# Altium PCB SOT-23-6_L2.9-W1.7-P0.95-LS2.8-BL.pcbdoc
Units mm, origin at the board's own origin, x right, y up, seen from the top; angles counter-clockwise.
Board outline 15.98 x 15.98 mm, 2 copper layers (Top Layer, Bottom Layer), stack 0 mm thick; 1 components, 0 nets, 6 pads, 0 vias.
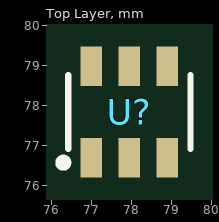
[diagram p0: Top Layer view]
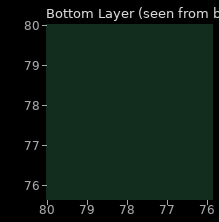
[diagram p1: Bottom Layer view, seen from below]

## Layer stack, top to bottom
Top Layer: signal copper (thickness not stored)
Bottom Layer: signal copper (thickness not stored)

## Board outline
85.827,69.85 69.85,69.85 69.85,85.83 85.827,85.83

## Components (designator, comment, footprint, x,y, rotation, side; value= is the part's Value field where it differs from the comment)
U? "" SOT-23-6_L2.9-W1.7-P0.95-LS2.8-BL 77.951,77.84 r0 top

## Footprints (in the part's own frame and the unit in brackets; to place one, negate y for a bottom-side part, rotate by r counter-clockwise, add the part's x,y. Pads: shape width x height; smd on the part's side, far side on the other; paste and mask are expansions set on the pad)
SOT-23-6_L2.9-W1.7-P0.95-LS2.8-BL [mm]
  rect 0.532x0.99 smd: 1(-0.95,-1.145) 2(0,-1.145) 3(0.95,-1.145) 4(0.95,1.145) 5(0,1.145) 6(-0.95,1.145)
  silkscreen extent -1.75,-1.37 1.53,0.93

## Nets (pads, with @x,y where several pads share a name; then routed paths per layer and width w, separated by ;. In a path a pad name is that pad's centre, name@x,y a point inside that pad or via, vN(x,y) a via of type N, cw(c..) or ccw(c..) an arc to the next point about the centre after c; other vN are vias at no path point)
pads on no net: U?.1 U?.2 U?.3 U?.4 U?.5 U?.6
